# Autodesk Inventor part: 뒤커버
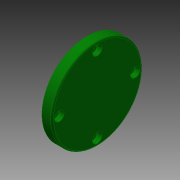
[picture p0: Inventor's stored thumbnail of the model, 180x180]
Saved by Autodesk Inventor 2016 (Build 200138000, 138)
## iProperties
Created: 2015-09
Part Number: 뒤커버
Material: 알루미늄 6061
Document SubType Name: Modeling
Designer: mduedu
Density: 2.71 g/cm^3
Mass: 54.0417 g
Surface Area: 84.9688 cm^2
Volume: 19.9416 cm^3
Appearance: 진녹색
Author: mduedu
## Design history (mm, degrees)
sketch "스케치1"
  geometry: L1 (-15.5, 47)-(-15.5, 78); L2 (-15.5, 78)-(-22.5, 78); L3 (-22.5, 78)-(-22.5, 67); L4 (-25.5, 67)-(-25.5, 47); L5 (-79.5, 39.5)-(-79.5, 54.5) reference; L6 (48.5, 54.5)-(48.5, 39.5) reference; L7 (-79.5, 47)-(48.5, 47); L8 (-22.5, 67)-(-25.5, 67); L9 (-25.5, 47)-(-15.5, 47); 1 further point
  constraints: 14 end point, 4 midpoint, 3 parallel, 1 collinear, 1 point on line, 1 vertical
  dimensions: "d6" = 62 diameter of L2 L7; "d7" = 7 distance of L1.end L2.end; "d8" = 40 diameter of L3.end L7; "d32" = 10 distance between parallel lines of L1 L4
revolve "회전1" sketch "스케치1" stored, may be unused: angle "d4" = 90 deg
sketch "스케치4"
  geometry: C1 r 31 at (0, 0) reference; 2 further points
  constraints: 1 coincident
hole "구멍3" sketch "스케치4" at (0, 0) diameter "d33" = 33; stored, may be unused: countersink angle "d37" = 90 deg, drill point angle "d39" = 0 deg; dims "d34" = 6, "d35" = 4, "d36" = 2, "d38" = 5
fillet "모깎기4" dims "d40" = 1, "d61" = 3
chamfer "모따기2" distance "d41" = 1; stored, may be unused: second distance "d42" = 2, angle "d43" = 45 deg
sketch "스케치6" dims "d56" = 52
  geometry: C1 r 31 at (0, 0) reference; 5 further points
  constraints: 2 vertical alignment, 1 coincident, 7 other
  dimensions: "d59" = 360 deg dimension on C1.centre point (0, 26) (derived)
hole "구멍4" sketch "스케치6" at (0, 26), (-26, 0), (0, -26), (26, 0) diameter "d49" = 3.4; stored, may be unused: countersink angle "d53" = 90 deg, drill point angle "d55" = 0 deg; dims "d50" = 6, "d51" = 6.5, "d52" = 3.4, "d54" = 8
node "솔리드1"
node "참조1"
node "참조2"
